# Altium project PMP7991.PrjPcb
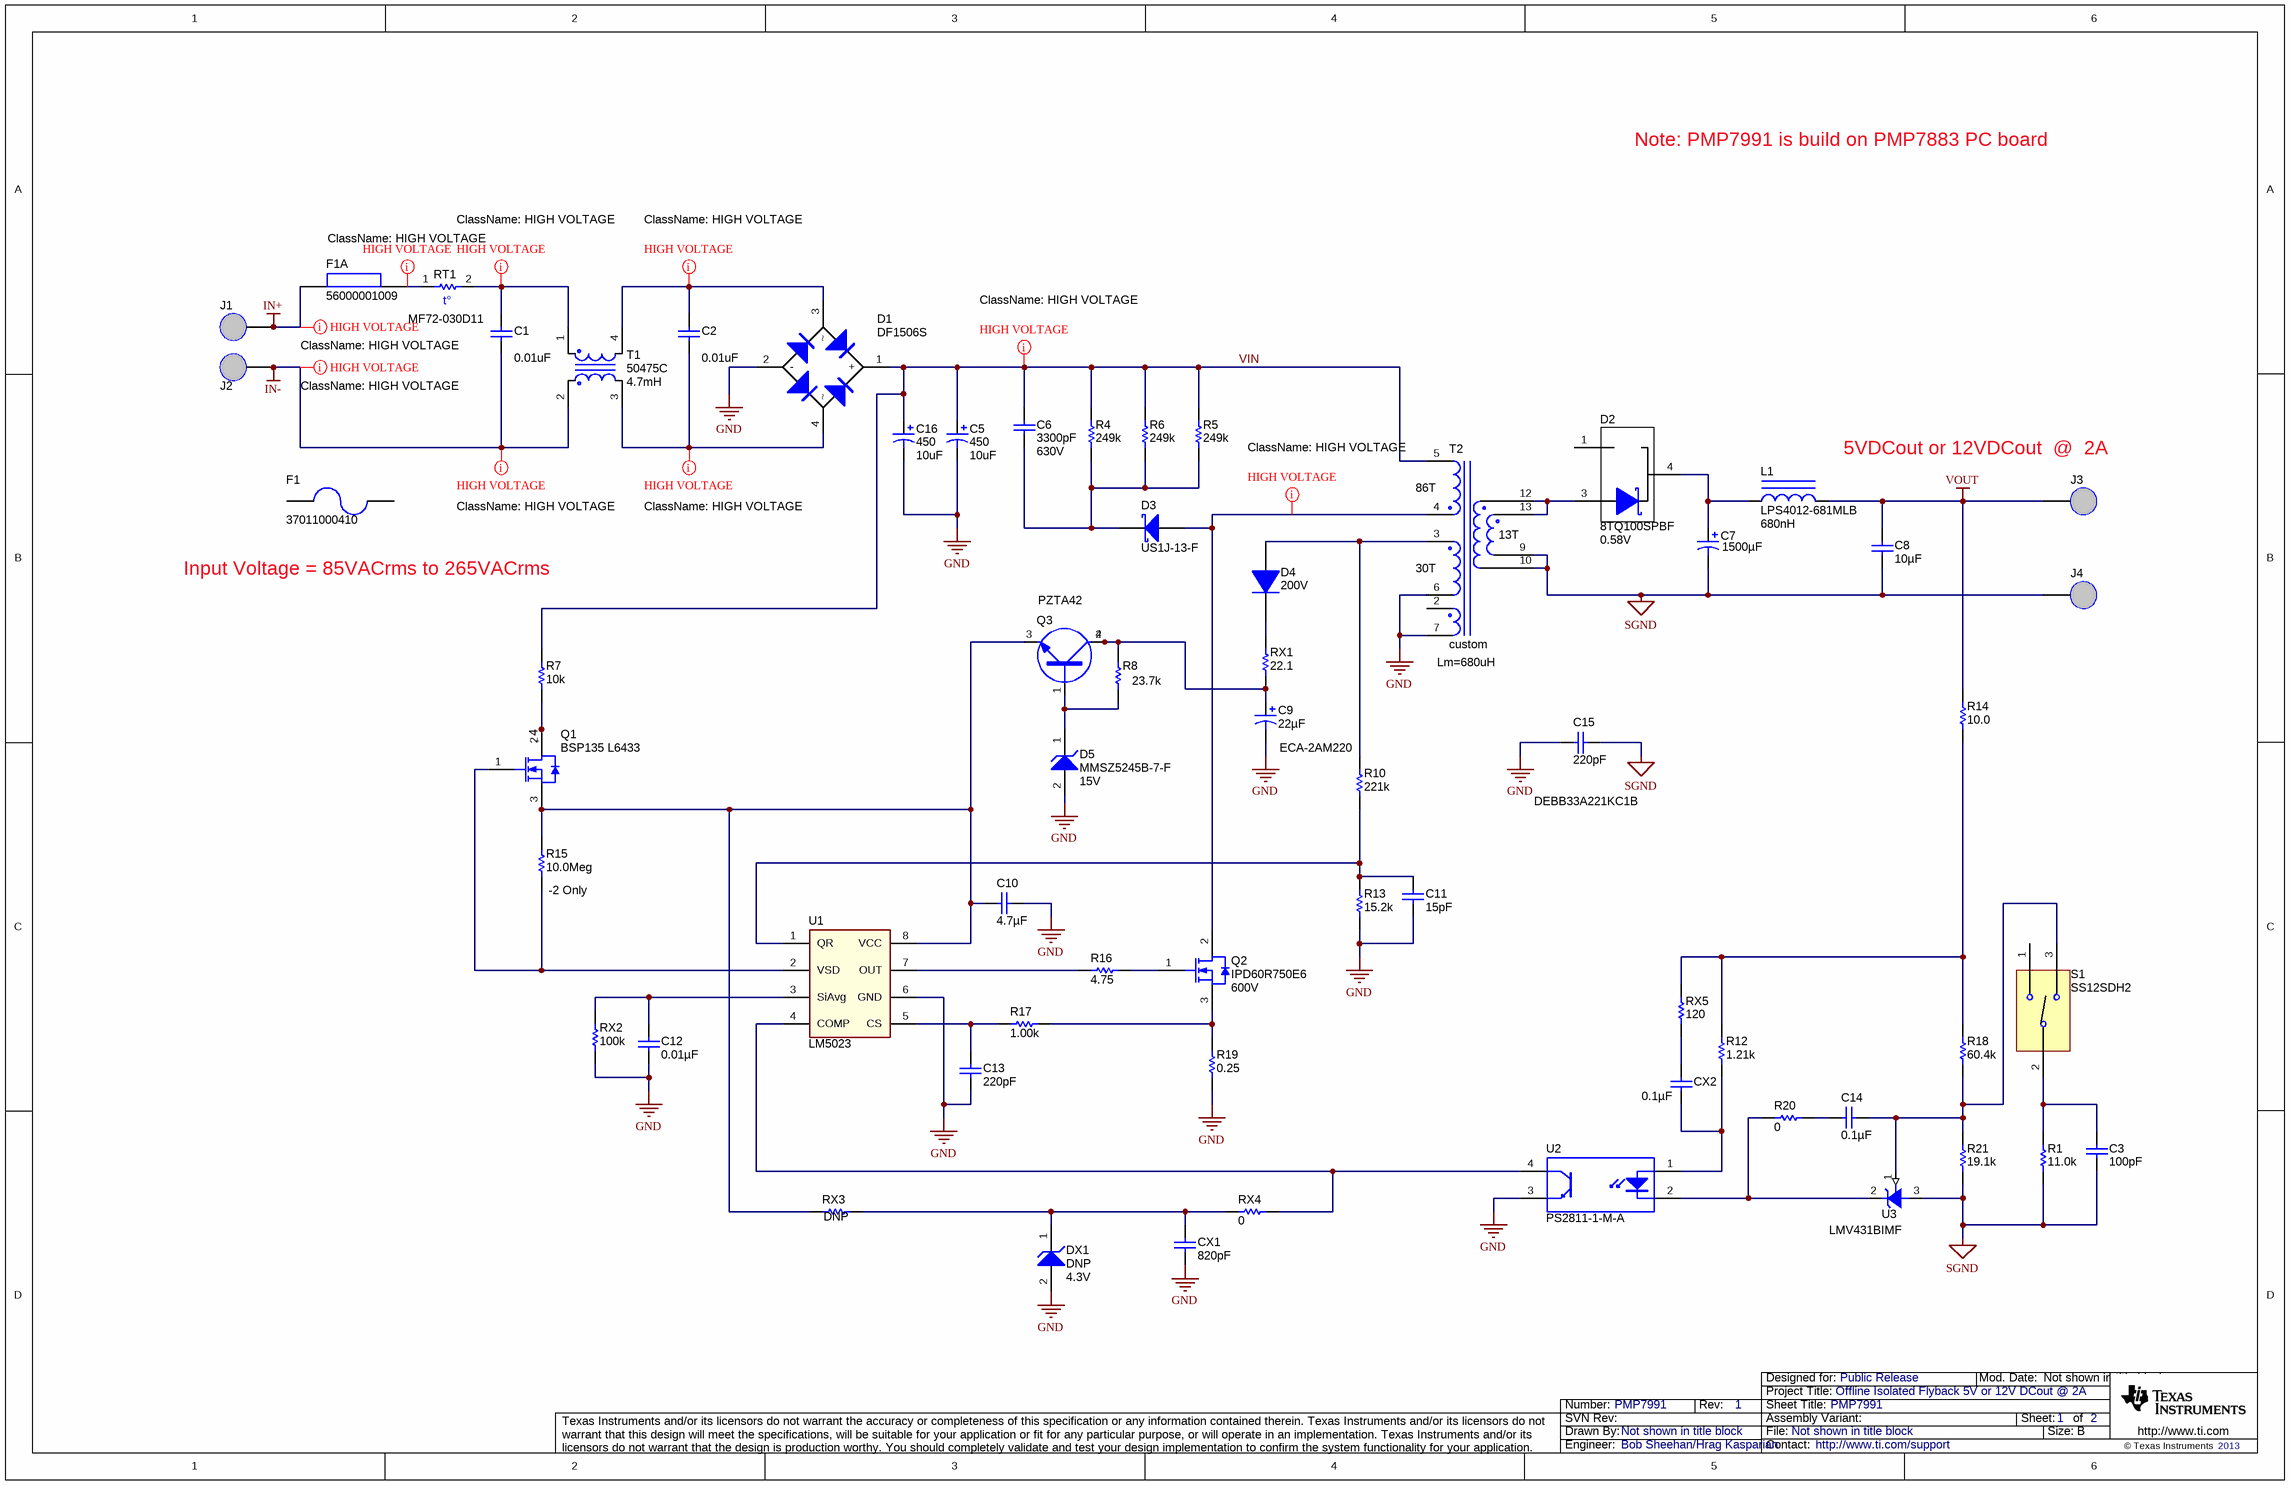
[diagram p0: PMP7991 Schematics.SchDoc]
TID: PMP7991; TechSupport: http://www.ti.com/support; SCH_Rev: 1; PRJ_Title: Offline Isolated Flyback 5V or 12V DCout @ 2A; PRJ_Number: PMP7991; PRJ_Engineer: Bob Sheehan/Hrag Kasparian; PRJ_Customer: Public Release; PCB_Rev: C; PCB_Layout: Bob Sheehan/Hrag Kasparian; CopyrightYear: 2013
2 sheets, 72 parts. Net scope: global (net labels, ports and power ports of the same name join across sheets).
Board file: PMP7883 REVC.PcbDoc
Sheets:
  PMP7991 Schematics.SchDoc
  PMP7991_Hardware_ANSI-B.SchDoc

## Sheet PMP7991 Schematics.SchDoc: PMP7991
size 431 x 279 mm; Date: Not shown in title block; ApprovedBy: Not shown in title block; CheckedBy: Not shown in title block; Author: Not shown in title block; CompanyName: Not shown in title block; DrawnBy: Not shown in title block; Engineer: Not shown in title block; Organization: Not shown in title block; Address1: Not shown in title block; Address2: Not shown in title block; Address3: Not shown in title block; Address4: Not shown in title block; DocumentNumber: 1; Revision: Use project parameter SCH_Rev; SheetNumber: 1; SheetTotal: 2; PageSetup: Record=PageOptions¦CenterHorizontal=True¦CenterVertical=True¦PrintScale=1.09¦XCorrection=1.00¦YCorrection=1.00¦PrintKind=1¦BorderSize=5000000¦LeftOffset=0¦BottomOffset=0¦Orientation=2¦PaperLength=1000¦PaperWidth=1000¦Scale=100¦PaperSource=15¦PrintQuality=600¦MediaType=1¦DitherType=10¦PaperKind=11x17¦PrintScaleMode=1

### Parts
C1  Value Displayed: 0.01uF  [VY2103M63Y5US63V7]  (hidden comment: BC2361-ND)
C2  Value Displayed: 0.01uF  [VY2103M63Y5US63V7]  (hidden comment: BC2361-ND)
C3  ValueDisplayed: 100pF  [0603]  (hidden comment: 06035A101JAT2A)
C5  VDC_V: 450  Value Displayed: 10uF  [EEUEE2W100U]  (hidden comment: EEU-EE2W100U)
C6  ValueDisplayed: 3300pF  Value2: 630V  [1206]  (hidden comment: C3216C0G2J332J)
C7  Capacitance: 1500µF  [10 X 20 HM]  (hidden comment: UHM1C152MPD)
C8  ValueDisplayed: 10µF  [0805_HV]  (hidden comment: 0805YD106MAT2A)
C9  ECA-2AM220  Capacitance: 22µF  [PANASONIC M]
C10  ValueDisplayed: 4.7µF  [1206]  (hidden comment: C3216X7R1E475K)
C11  ValueDisplayed: 15pF  [0603]  (hidden comment: GRM1885C1H150JA01D)
C12  ValueDisplayed: 0.01µF  [0603]  (hidden comment: C1608C0G1E103J)
C13  ValueDisplayed: 220pF  [0402]  (hidden comment: GRM1555C1H221JA01D)
C14  ValueDisplayed: 0.1µF  [0603]  (hidden comment: C0603C104K5RACTU)
C15  DEBB33A221KC1B  ValueDisplayed: 220pF  [MURATA C1]
C16  VDC_V: 450  Value Displayed: 10uF  [EEUEE2W100U]  (hidden comment: EEU-EE2W100U)
CX1  ValueDisplayed: 820pF  [0603]  (hidden comment: C0603C821J5GACTU)
CX2  ValueDisplayed: 0.1µF  [0603]  (hidden comment: C1608X7R1H104K)
D1  DF1506S  [DF-S]
D2  8TQ100SPBF  value 0.58V  [DDPAK]
D3  US1J-13-F  [SMA]
D4  Value2: 200V  [SOD-123]  (hidden comment: RF071M2S)
D5  MMSZ5245B-7-F  value 15V  [SOD-123]
DX1  DNP  value 4.3V  [SOD-123]
F1  37011000410  [37011000410]
F1A  56000001009  [56000001009]
J1  TH PAD  [TH PAD]  (value not drawn)
J2  TH PAD  [TH PAD]  (value not drawn)
J3  TH PAD  [TH PAD]  (value not drawn)
J4  TH PAD  [TH PAD]  (value not drawn)
L1  LPS4012-681MLB  ValueDisplayed: 680nH  [LPS4012]
Q1  BSP135 L6433  [SOT-223]
Q2  IPD60R750E6  value 600V  [PG TO252-3]
Q3  PZTA42,115  [SOT-223]  (value not drawn)
R1  value 11.0k  [0603]  (hidden comment: CRCW060311K0FKEA)
R4  value 249k  [1206]  (hidden comment: CRCW1206249KFKEA)
R5  value 249k  [1206]  (hidden comment: CRCW1206249KFKEA)
R6  value 249k  [1206]  (hidden comment: CRCW1206249KFKEA)
R7  10k  [2512]
R8  Resistance (Ohms): 23.7k  [0603]  (hidden comment: RC0603FR-0723K7L)
R10  value 221k  [0603]  (hidden comment: CRCW0603221KFKEA)
R12  value 1.21k  [0603]  (hidden comment: CRCW06031K21FKEA)
R13  value 15.2k  [0603]  (hidden comment: RT0603DRE0715K2L)
R14  value 10.0  [0603]  (hidden comment: CRCW060310R0FKEA)
R15  value 10.0Meg  [1206]  (hidden comment: CRCW120610M0FKEA)
R16  value 4.75  [0603]  (hidden comment: CRCW06034R75FKEA)
R17  value 1.00k  [0603]  (hidden comment: CRCW06031K00FKEA)
R18  value 60.4k  [0603]  (hidden comment: CRCW060360K4FKEA)
R19  value 0.25  [1206]  (hidden comment: CSR1206FKR250)
R20  value 0  [0603]  (hidden comment: CRCW06030000Z0EA)
R21  value 19.1k  [0603]  (hidden comment: CRCW060319K1FKEA)
RT1  MF72-030D11  [MF72-D11_02]
RX1  value 22.1  [0603]  (hidden comment: RC0603FR-0722R1L)
RX2  value 100k  [0603]  (hidden comment: RC0603FR-07100KL)
RX3  DNP  [0603]
RX4  value 0  [0603]  (hidden comment: CRCW06030000Z0EA)
RX5  value 120  [0603]  (hidden comment: RC0603FR-07120RL)
S1  SS12SDH2  [SS12SDH2]
T1  50475C  Value Displayed: 4.7mH  [50475C]
T2  custom  [7508112324_0]
U1  LM5023  [MUA08A_L]
U2  PS2811-1-M-A  [PS2811-1]
U3  LMV431BIMF  [MF03A_N]

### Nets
GND: C5.2(-) C9.2(-) C10.1 C11.2 C12.2 C13.2 C15.2 C16.2(-) CX1.2 D1.2(-) D5.2(A) DX1.2(A) R13.1 R19.1 RX2.1 T2.6 T2.7 U1.6(GND) U2.3(E)
IN+: F1A.2 J1.1
IN-: C1.2 J2.1 T1.2
SGND: C3.2 C7.2(-) C8.2 C15.1 J4.1 R1.1 R21.1 T2.9 T2.10 U3.3(A)
VOUT: C8.1 J3.1 L1.2 R14.2
VIN: C5.1(+) C6.1 C16.1(+) D1.1(+) R4.1 R5.2 R6.1 R7.2 T2.5
NetC1_1: C1.1 RT1.2 T1.1
NetC2_1: C2.1 D1.3 T1.4
NetC2_2: C2.2 D1.4 T1.3
NetC3_1: C3.1 R1.2 S1.2(COM)
NetC6_2: C6.2 D3.1(K) R4.2 R5.1 R6.2
NetC7_1: C7.1(+) D2.4(K) L1.1
NetC9_1: C9.1(+) Q3.2(C) Q3.4(C) R8.2 RX1.1
NetC10_2: C10.2 Q1.3(S) Q3.3(E) R15.2 RX3.2 U1.8(VCC)
NetC11_1: C11.1 R10.1 R13.2 U1.1(QR)
NetC12_1: C12.1 RX2.2 U1.3(SiAvg)
NetC13_1: C13.1 R17.1 U1.5(CS)
NetC14_1: C14.1 R18.1 R21.2 S1.3(CLOSE) U3.1(REF)
NetC14_2: C14.2 R20.2
NetCX1_1: CX1.1 DX1.1(K) RX3.1 RX4.2
NetCX2_1: CX2.1 RX5.1
NetCX2_2: CX2.2 R12.1 U2.1(A)
NetD2_3: D2.3(A) T2.12 T2.13
NetD3_2: D3.2(A) Q2.2(D) T2.4
NetD4_1: D4.1(K) RX1.2
NetD4_2: D4.2(A) R10.2 T2.3
NetD5_1: D5.1(K) Q3.1(B) R8.1
NetF1A_1: F1A.1 RT1.1
NetQ1_1: Q1.1(G) R15.1 U1.2(VSD)
NetQ1_2: Q1.2(D) Q1.4(D) R7.1
NetQ2_1: Q2.1(G) R16.2
NetQ2_3: Q2.3(S) R17.2 R19.2
NetR12_2: R12.2 R14.1 R18.2 RX5.2
NetR16_1: R16.1 U1.7(OUT)
NetR20_1: R20.1 U2.2(K) U3.2(K)
NetRX4_1: RX4.1 U1.4(COMP) U2.4(C)

Not connected (* = marked no-connect by the designer): D2 1(A); S1 1(OPEN); T2 2

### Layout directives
net class HIGH VOLTAGE: IN+, IN-, NetC1_1, NetC2_1, NetC2_2, NetD3_2, NetF1A_1, VIN

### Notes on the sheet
- Note: PMP7991 is build on PMP7883 PC board
- (near T2) 86T
- 5VDCout or 12VDCout  @  2A
- Input Voltage = 85VACrms to 265VACrms
- (near T2) 30T
- (near T2) 13T
- (near T2) Lm=680uH
- (near R15) -2 Only

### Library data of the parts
C1 C2 = VY2103M63Y5US63V7: CAP CER 10000PF 300V 20% RADIAL; Manufacturer: Vishay; SymbolCreator: bkinsc; U/M: EA; Tolerance_%: 20; TaMax_C: 125; TaMin_C: -40; Value: 0.01uF
C3 = 06035A101JAT2A: CAP, CERM, 100pF, 50V, +/-5%, C0G/NP0, 0603; Manufacturer: AVX; Polarized: N; CompType: Capacitor; U/M: EA; Cap_F: 0.0000000001; Tolerance_%: 5; ESR_Ohm: 0.119; Value1: 0.119 ohm; VDC_V: 50; TaMin_C: -55; TaMax_C: 125
C5 C16 = EEUEE2W100U: CAP ALUM 10UF 450V 20% RADIAL; Manufacturer: Panasonic; SymbolCreator: bkinsc; U/M: EA, IN, or GM; TaMax_C: 105; TaMin_C: -55; Tolerance_%: 20
C6 = C3216C0G2J332J: CAP, CERM, 3300pF, 630V, +/-5%, C0G/NP0, 1206; Manufacturer: TDK; Polarized: N; CompType: Capacitor; U/M: EA; Cap_F: 0.0000000033; Tolerance_%: 5; ESR_Ohm: 0.0369; Value1: 0.0369 ohm; VDC_V: 630; TaMin_C: -55; TaMax_C: 125
C7 = Capacitor_Polarized: CAP, [CAP ALUM 1500UF 16V 20% RADIAL; Manufacturer: Nichicon; Lifetime @ Temp.: 2000 Hrs @ 105°C; Ripple Current: 2.55A; Impedance: 13 mOhm
C8 = 0805YD106MAT2A: CAP, CERM, 10uF, 16V, +/-20%, X5R, 0805; Manufacturer: AVX; Polarized: N; CompType: Capacitor; U/M: EA; Cap_F: 0.00001; Tolerance_%: 20; VDC_V: 16; TaMin_C: -55; TaMax_C: 85; Cap_Case: 0805
C9 = ECA-2AM220: CAP ALUM 22UF 100V 20% RADIAL; Manufacturer: Panasonic Electronic Components; Lifetime @ Temp.: 2000 Hrs @ 85°C; Ripple Current: .115A
C10 = C3216X7R1E475K: CAP, CERM, 4.7uF, 25V, +/-10%, X7R, 1206; Manufacturer: TDK; Polarized: N; CompType: Capacitor; U/M: EA; Cap_F: 0.0000047; Tolerance_%: 10; ESR_Ohm: 0.0063; Value1: 0.0063 ohm; VDC_V: 25; TaMin_C: -55; TaMax_C: 125
C11 = GRM1885C1H150JA01D: CAP, CERM, 15pF, 50V, +/-5%, C0G/NP0, 0603; Manufacturer: MuRata; Polarized: N; CompType: Capacitor; U/M: EA; Cap_F: 0.000000000015; Tolerance_%: 5; Value1: Unknown; VDC_V: 50; TaMin_C: -55; TaMax_C: 125
C12 = C1608C0G1E103J: CAP, CERM, 0.01uF, 25V, +/-5%, C0G/NP0, 0603; Manufacturer: TDK; Polarized: N; CompType: Capacitor; U/M: EA; Cap_F: 0.00000001; Tolerance_%: 5; VDC_V: 25; TaMin_C: -55; TaMax_C: 125
C13 = GRM1555C1H221JA01D: CAP, CERM, 220pF, 50V, +/-5%, C0G/NP0, 0402; Manufacturer: MuRata; Polarized: N; CompType: Capacitor; U/M: EA; Cap_F: 0.00000000022; Tolerance_%: 5; VDC_V: 50; TaMin_C: -55; TaMax_C: 125
C14 = C0603C104K5RACTU: CAP, CERM, 0.1uF, 50V, +/-10%, X7R, 0603; Manufacturer: Kemet; Polarized: N; CompType: Capacitor; U/M: EA; Cap_F: 0.0000001; Tolerance_%: 10; Value1: Unknown; VDC_V: 50; TaMin_C: -55; TaMax_C: 125
C15 = DEBB33A221KC1B: CAP CER 220PF 1KV 10% RADIAL; Manufacturer: Murata Electronics North America; Polarized: N; CompType: Capacitor; U/M: EA; Cap_F: 0.0000000022; Tolerance_%: 10; VDC_V: 1000; Value2: 1000V; TaMin_C: -55; TaMax_C: 125; Cap_Case: 1812
CX1 = C0603C821J5GACTU: CAP, CERM, 820pF, 50V, +/-5%, C0G/NP0, 0603; Manufacturer: Kemet; Polarized: N; CompType: Capacitor; U/M: EA; Cap_F: 0.00000000082; Tolerance_%: 5; Value1: Unknown; VDC_V: 50; TaMin_C: -55; TaMax_C: 125
CX2 = C1608X7R1H104K: CAP, CERM, 0.1uF, 50V, +/-10%, X7R, 0603; Manufacturer: TDK; Polarized: N; CompType: Capacitor; U/M: EA; Cap_F: 0.0000001; Tolerance_%: 10; ESR_Ohm: 0.017; Value1: 0.017 ohm; VDC_V: 50; TaMin_C: -55; TaMax_C: 125
D1 = DF1506S: Diode, Switching-Bridge, 600V, 1.5A, DF-S; Manufacturer: Diodes Inc.; Value: 1.1V; U/M: EA; Vf_V: 1.1; Io_A: 1.5; Vr_V: 600; TJmax_C: 150
D2 = 8TQ100SPBF: DIODE SCHOTTKY 100V 8A D2PAK; Manufacturer: Vishay-Semiconductor; Alternate Manufacturer: Any; Alternate PartNumber: Equivalent; U/M: EA; Vf_V: 0.56; Io_A: 8; Vr_V: 100; TJmax_C: 175
D3 = SS14-E3/61T: Diode, Schottky, 600V, 1A, SMA; Manufacturer: Diodes Inc; Value: 1.7V; U/M: EA; Vf_V: 1.7; Io_A: 1; Vr_V: 600; TJmax_C: 125; RJC_CperW: 30; Type: Fast
D4 = RF071M2S: Diode, Ultrafast, 200V, 1A, SOD-123; Manufacturer: Rohm; Value: 0.85V; U/M: EA; Vf_V: 0.85; Io_A: 1; Vr_V: 200; TJmax_C: 150
D5 = MMSZ5245B-7-F: Diode, Zener, 15V, 500mW, SOD-123; Manufacturer: Diodes Inc.; U/M: EA; Power_W: 0.5; Vz_V: 15; Value1: 0.5W; RJA_CperW: 350
DX1 = MMSZ5229B-7-F: Diode, Zener, 4.3V, 500mW, SOD-123; Manufacturer: Diodes Inc.; U/M: EA; Power_W: 0.5; Value1: 0.5W; RJA_CperW: 350; Vz: 4.3
F1 = 37011000410: FUSE FAST 250VAC 1A RADIAL; Manufacturer: Littelfuse Inc; SymbolCreator: bkinsc; U/M: EA; DC Cold Resistance: 0.0676 Ohm; Breaking Capacity @ Rated Voltage: 50A; Melting I²t: 0.2; Fuse Type: Board Mount (Cartridge Style Excluded); Approvals: CCC, cULus, PSE/JET, SEMKO, VDE; Voltage Rating - AC: 250V
F1A = 56000001009: Fuseholders, Clips, & Hardware 6.3A/1.6W/4.3mm TR5/TE5 Holder; Manufacturer: Littlefuse; SymbolCreator: bkinsc; U/M: EA
J1-J4 = TH PAD: THROUGH HOLE PAD; Manufacturer: NONE; SymbolVersion: use current date i.e. 2008-05-20; SymbolCreator: Use a-id; CompType: Used in some BOM reports.  Useful for finding later.; U/M: EA
L1 = LPS4012-681MLB: Inductor, Shielded Drum Core, Ferrite, 680nH, 2.4A, 0.05 ohm, SMD; Manufacturer: Coilcraft; Alternate Manufacturer: Any; Alternate PartNumber: Equivalent; Ind_H: 680.0E-9; Imax_A: 2.4; Irms: 2.4A @ 40C rise; Isat: 3.7A @ 30% inductance drop; DCR_ohm: 0.05; U/M: EA
Q1 = BSP135: MOSFET N-CH 600V 120MA SOT-223; Manufacturer: Infineon; SymbolCreator: bkinsc; CompType: FET; U/M: EA
Q2 = IPD60R750E6: MOSFET N-CH 600V 5.7A TO252-3; Manufacturer: Infineon Technologies; U/M: EA; ChType: N; VdsMax_V: 600; Value1: .68 ohm; Value2: 17.2 nC; QgTyp_nC: 17.2; Vgs_V: 30; IdsMax_A: 5.7
Q3 = PZTA42: TRANS NPN 300V 100MA SOT223; Manufacturer: Fairchild Semiconductor; Current - Collector (Ic) (Max): 500mA; Vce Saturation (Max) @ Ib, Ic: 500mV @ 2mA, 20mA; DC Current Gain (hFE) (Min) @ Ic, Vce: 40 @ 30mA, 10V; Power - Max: 1W; Frequency - Transition: 50MHz
R1 = CRCW060311K0FKEA: RES, 11.0k ohm, 1%, 0.1W, 0603; Manufacturer: Vishay-Dale; CompType: Resistor; Res_ohm: 11000; Value_Code: 11k0; Tolerance_%: 1; Power_W: 0.1; VDC_V: 75; TempCo: 100 ppm/C; EIA_Code: E96; U/M: EA
R4-R6 = CRCW1206249KFKEA: RES, 249k ohm, 1%, 0.25W, 1206; Manufacturer: Vishay-Dale; CompType: Resistor; Res_ohm: 249000; Tolerance_%: 1; Power_W: 0.25; VDC_V: 200; TempCo: 100 ppm/C; EIA_Code: E96; U/M: EA
R7 = CRCW251210K0FKEGHP: RES 10.0K OHM 1W 1% 2512 SMD; Manufacturer: Vishay Dale; SymbolVersion: use current date i.e. 2008-05-20; SymbolCreator: Use LDAP id; CompType: Used in some BOM reports.  Useful for finding later.; U/M: EA, IN, or GM; Power_W: 1.5W; TempCo: ±100ppm/°C
R8 = Resistor: RES 23.7K OHM 1/10W 1% 0603 SMD; Manufacturer: Yageo; Power (Watts): 0.1W, 1/10W; Temperature Coefficient: ±100ppm/°C
R10 = CRCW0603221KFKEA: RES, 221k ohm, 1%, 0.1W, 0603; Manufacturer: Vishay-Dale; CompType: Resistor; Res_ohm: 221000; Tolerance_%: 1; Power_W: 0.1; VDC_V: 75; TempCo: 100 ppm/C; EIA_Code: E96; U/M: EA
R12 = CRCW06031K21FKEA: RES, 1.21k ohm, 1%, 0.1W, 0603; Manufacturer: Vishay-Dale; CompType: Resistor; Res_ohm: 1210; Value_Code: 1k21; Tolerance_%: 1; Power_W: 0.1; VDC_V: 75; TempCo: 100 ppm/C; EIA_Code: E96; U/M: EA
R13 = RT0603DRE0715K2L: RES, 15.2k ohm, 0.5%, 0.1W, 0603; Manufacturer: Yageo America; CompType: Resistor; Res_ohm: 15200; Value_Code: 15k2; Tolerance_%: 0.5; Power_W: 0.1; VDC_V: 75; TempCo: 50 ppm/C; EIA_Code: E192; U/M: EA
R14 = CRCW060310R0FKEA: RES, 10.0 ohm, 1%, 0.1W, 0603; Manufacturer: Vishay-Dale; CompType: Resistor; Res_ohm: 10; Value_Code: 10R0; Tolerance_%: 1; Power_W: 0.1; VDC_V: 75; TempCo: 100 ppm/C; EIA_Code: E96; U/M: EA
R15 = CRCW120610M0FKEA: RES, 10.0Meg ohm, 1%, 0.25W, 1206; Manufacturer: Vishay-Dale; CompType: Resistor; Res_ohm: 10000000; Value_Code: 10M0; Tolerance_%: 1; Power_W: 0.25; VDC_V: 200; TempCo: 100 ppm/C; EIA_Code: E96; U/M: EA
R16 = CRCW06034R75FKEA: RES, 4.75 ohm, 1%, 0.1W, 0603; Manufacturer: Vishay-Dale; CompType: Resistor; Value_Code: 4R75; Tolerance_%: 1; Power_W: 0.1; VDC_V: 75; TempCo: 100 ppm/C; EIA_Code: E96; U/M: EA
R17 RX3 = CRCW06031K00FKEA: RES, 1.00k ohm, 1%, 0.1W, 0603; Manufacturer: Vishay-Dale; CompType: Resistor; Res_ohm: 1000; Value_Code: 1k00; Tolerance_%: 1; Power_W: 0.1; VDC_V: 75; TempCo: 100 ppm/C; EIA_Code: E96; U/M: EA
R18 = CRCW060360K4FKEA: RES, 60.4k ohm, 1%, 0.1W, 0603; Manufacturer: Vishay-Dale; CompType: Resistor; Res_ohm: 60400; Value_Code: 60k4; Tolerance_%: 1; Power_W: 0.1; VDC_V: 75; TempCo: 100 ppm/C; EIA_Code: E96; U/M: EA
R19 = CSR1206FKR250: RES, 0.25 ohm, 1%, 0.5W, 1206; Manufacturer: Stackpole Electronics Inc; CompType: Resistor; Value_Code: R250; Tolerance_%: 1; Power_W: 0.5; TempCo: 100 ppm/C; U/M: EA
R20 RX4 = CRCW06030000Z0EA: RES, 0 ohm, 5%, 0.1W, 0603; Manufacturer: Vishay-Dale; CompType: Resistor; Value_Code: 0000; Tolerance_%: 5; Power_W: 0.1; VDC_V: 75; TempCo: 200 ppm/C; EIA_Code: E24; U/M: EA
R21 = CRCW060319K1FKEA: RES, 19.1k ohm, 1%, 0.1W, 0603; Manufacturer: Vishay-Dale; CompType: Resistor; Res_ohm: 19100; Value_Code: 19k1; Tolerance_%: 1; Power_W: 0.1; VDC_V: 75; TempCo: 100 ppm/C; EIA_Code: E96; U/M: EA
RT1 = MF72-030D11: CURRENT LIMITER INRUSH 30OHM 20%; Manufacturer: Cantherm; SymbolCreator: bkinsc; CompType: Used in some BOM reports.  Useful for finding later.; U/M: EA, IN, or GM; R @ Current: 0.667 Ohm; Current - Steady State Max: 1.5A
RX1 = RC0603FR-0722R1L: RES, 22.1 ohm, 1%, 0.1W, 0603; Manufacturer: Yageo America; CompType: Resistor; Value_Code: 22R1; Tolerance_%: 1; Power_W: 0.1; VDC_V: 150; TempCo: 200 ppm/C; EIA_Code: E96; U/M: EA
RX2 = RC0603FR-07100KL: RES, 100k ohm, 1%, 0.1W, 0603; Manufacturer: Yageo America; CompType: Resistor; Res_ohm: 100000; Tolerance_%: 1; Power_W: 0.1; VDC_V: 150; TempCo: 200 ppm/C; EIA_Code: E96; U/M: EA
RX5 = RC0603FR-07120RL: RES, 120 ohm, 1%, 0.1W, 0603; Manufacturer: Yageo America; CompType: Resistor; Value_Code: 120R; Tolerance_%: 1; Power_W: 0.1; VDC_V: 150; TempCo: 200 ppm/C; U/M: EA
S1 = SS12SDH2: SW SLIDE ULTR MINI SPDT SIDE ACT; Manufacturer: NKK; SymbolVersion: 2012 - 10 - 19; SymbolCreator: cdnlsc; CompType: Switch; U/M: EA
T1 = 50475C: CHOKE COMMON MODE 4.7MH 0.4A SMD; Manufacturer: Murata; SymbolCreator: bkinsc; CompType: Used in some BOM reports.  Useful for finding later.; U/M: EA; Vdc_V: 500; ZTyp@100KHz_Ohm: 18K
T2 = 7508112328: Werth Elektronik Transformer; Manufacturer: Werth Elekctronik; SymbolVersion: use current date i.e. 2008-05-20; SymbolCreator: Use LDAP id; U/M: EA
U1 = LM5023: IC, CTLR, AC-DC Quasi Resonant PWM; Manufacturer: Texas Instruments; SymbolCreator: bkinsc; U/M: EA, IN, or GM
U2 = PS2811-1-M-A: Low Input Current, Hight CTR Photocoupler; Manufacturer: Renesas; SymbolCreator: codlsc; CompType: OPTOCOUPLER; U/M: EA
U3 = LMV431BIMF: Low-Voltage (1.24V) Adjustable Precision Shunt Regulator, 3-pin SOT-23; Manufacturer: Texas Instruments; CompType: MiscPower; PackageTopMarking: RLB*XTT; PowerWise: N

## Sheet PMP7991_Hardware_ANSI-B.SchDoc
size 431 x 279 mm; Date: Not shown in title block; ApprovedBy: Not shown in title block; CheckedBy: Not shown in title block; Author: Not shown in title block; CompanyName: Not shown in title block; Engineer: Not shown in title block; Organization: Not shown in title block; Address1: Not shown in title block; Address2: Not shown in title block; Address3: Not shown in title block; Address4: Not shown in title block; DocumentNumber: 2; Revision: Use project parameter SCH_Rev; SheetNumber: 2; SheetTotal: 2; PageSetup: Record=PageOptions¦CenterHorizontal=True¦CenterVertical=True¦PrintScale=1.00¦XCorrection=1.00¦YCorrection=1.00¦PrintKind=0¦BorderSize=5000000¦LeftOffset=0¦BottomOffset=0¦Orientation=2¦PaperLength=1000¦PaperWidth=1000¦Scale=100¦PaperSource=15¦PrintQuality=600¦MediaType=1¦DitherType=10¦PaperKind=Letter¦PrintScaleMode=1
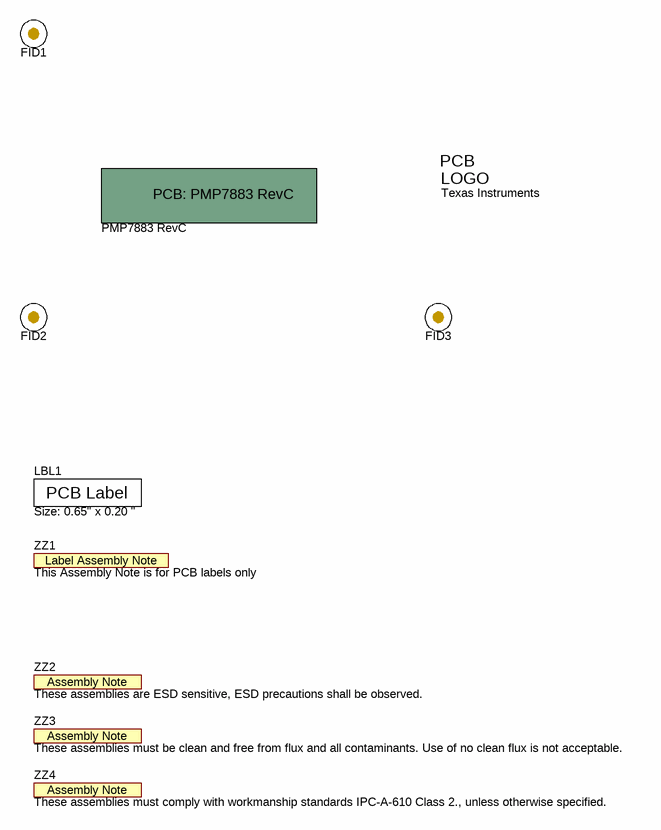
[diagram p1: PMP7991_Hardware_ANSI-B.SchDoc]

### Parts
!PCB?  PMP7883 RevC  (mechanical)
FID1  Fiducial  [Fiducial10-20]  (value not drawn)
FID2  Fiducial  [Fiducial10-20]  (value not drawn)
FID3  Fiducial  [Fiducial10-20]  (value not drawn)
LBL1  Size: 0.65" x 0.20 "  [Label_650x200]
Logo1  Texas Instruments  [TI_Stacked_SolderMask_Small]  (no BOM)
ZZ1  This Assembly Note is for PCB labels only  [AssemblyNoteLabel]  (no BOM)
ZZ2  These assemblies are ESD sensitive, ESD precautions shall be observed.  [AssemblyNote]  (no BOM)
ZZ3  These assemblies must be clean and free from flux and all contaminants. Use of no clean flux is not acceptable.  [AssemblyNote]  (no BOM)
ZZ4  These assemblies must comply with workmanship standards IPC-A-610 Class 2., unless otherwise specified.  [AssemblyNote]  (no BOM)

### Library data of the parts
!PCB? = PCB_OtherProject: Manufacturer: Any; SymbolCreator: a0412235; CompType: PCB; U/M: EA
FID1-FID3 = Fiducial: Fiducial mark.  There is nothing to buy or mount.; SymbolCreator: codlsc
LBL1 = THT-14-423-10: Thermal Transfer Printable Labels, 0.650" W x 0.200" H - 10,000 per roll; Manufacturer: Brady; SymbolCreator: a0412235; CompType: Label
Logo1 = TI_Logo: Texas Instrument Corporate Signature; SymbolCreator: codlsc
ZZ1 = AssemblyNoteLabel: SymbolCreator: a0412235
ZZ2-ZZ4 = AssemblyNote: SymbolCreator: codlsc

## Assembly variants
001: not fitted DX1 RX3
